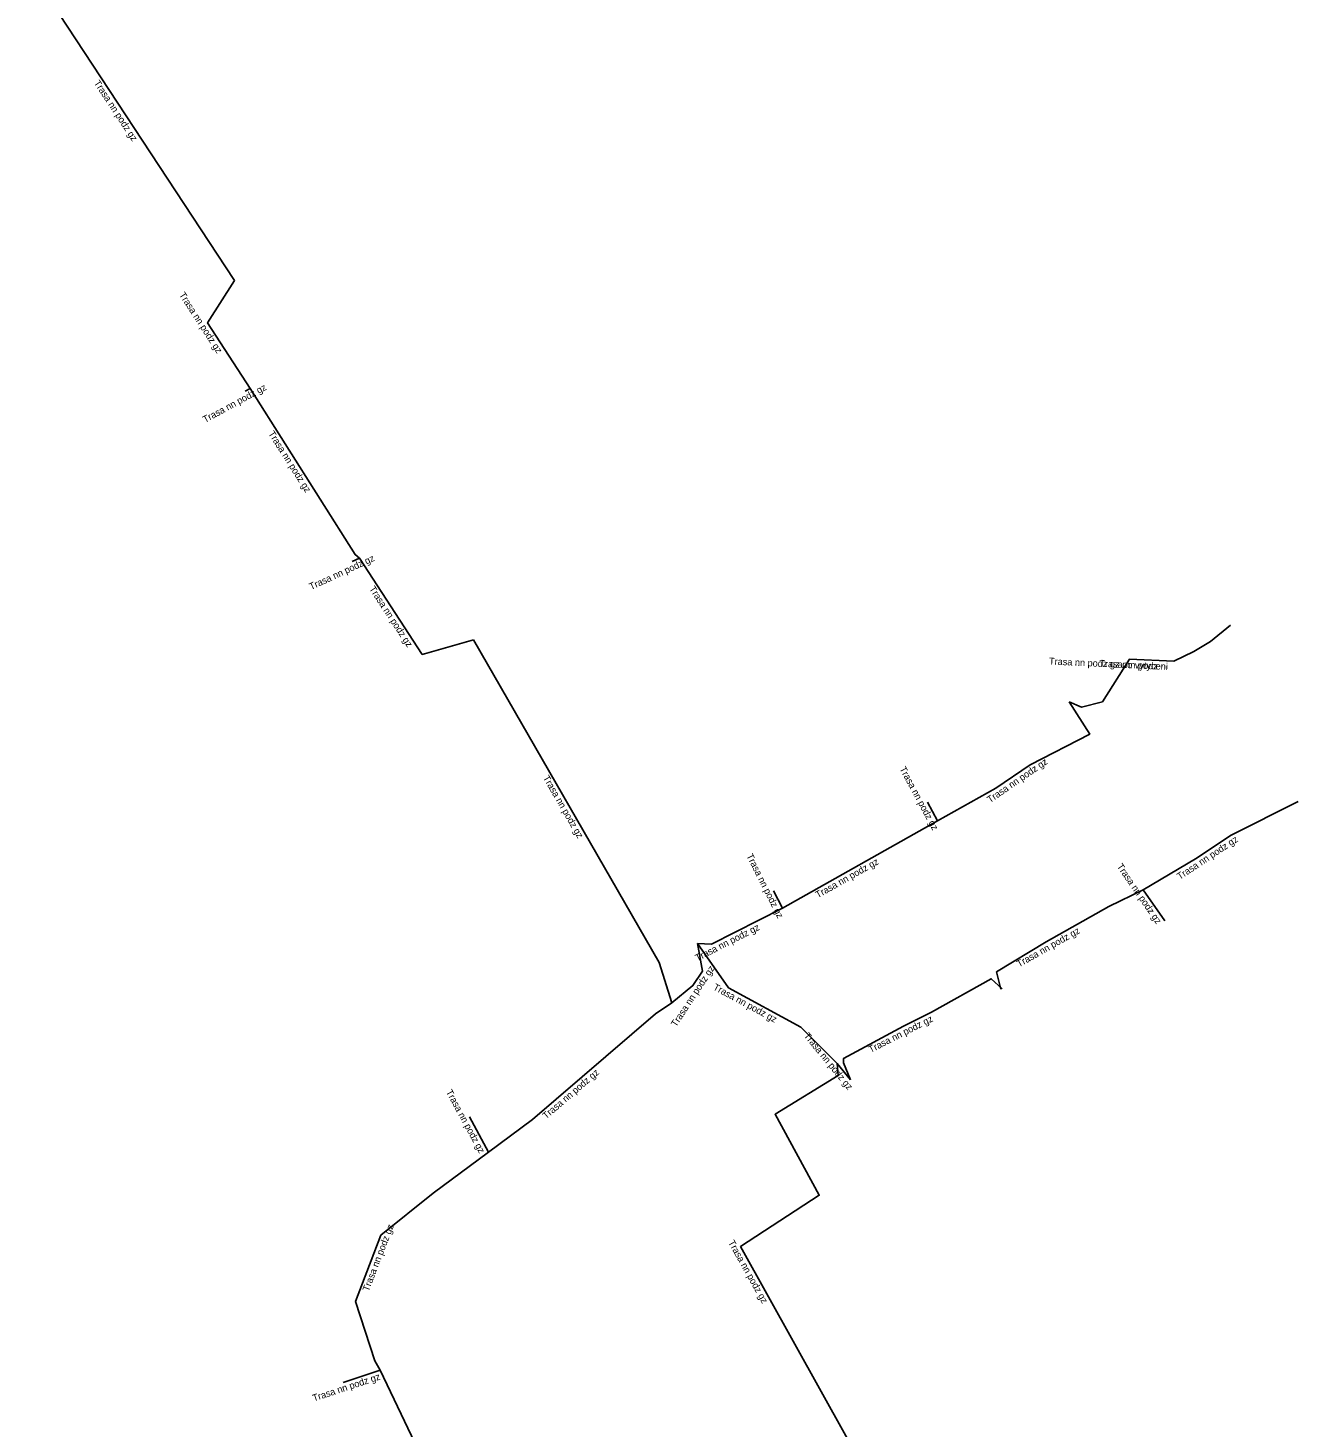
# Model space of a CAD drawing. Extents: x -467803 to -467116, y -1117596 to -1116713.
# Drawn here: x -467414.7 to -467321.9, y -1117056.5 to -1116954.2 of the extents above; entities that cross this region are included whole.
import ezdxf

# ---------------------------------------------------------------- set-up
doc = ezdxf.new("R2010")
doc.units = 0
for name, color, linetype in [('Popiskový text - Ostatní atributy Trasy', 7, 'Continuous'), ('Spojnice NN', 7, 'Continuous'), ('Spojnice VN', 7, 'Continuous')]:
    doc.layers.add(name, color=color, linetype=linetype)

msp = doc.modelspace()

# ---------------------------------------------------------------- linework, layer by layer
at = {"layer": 'Spojnice NN'}
for points in [[(-467399.6, -1116972.63), (-467413.05, -1116952.2), (-467414.68, -1116949.47)], [(-467398.45, -1116980.52), (-467401.56, -1116975.72), (-467399.6, -1116972.63)], [(-467398.45, -1116980.52), (-467398.8, -1116980.71)], [(-467390.46, -1116992.91), (-467390.77, -1116992.65), (-467398.45, -1116980.52)], [(-467390.46, -1116992.91), (-467390.98, -1116993.15)], [(-467382.11, -1116998.88), (-467385.86, -1116999.94), (-467390.46, -1116992.91)], [(-467338.58, -1117003.41), (-467337.68, -1117003.8), (-467336.15, -1117003.41), (-467334.17, -1117000.3), (-467330.93, -1117000.45), (-467329.47, -1116999.74), (-467328.25, -1116999), (-467326.79, -1116997.82)], [(-467338.58, -1117003.41), (-467337.68, -1117003.8), (-467336.15, -1117003.41), (-467334.17, -1117000.3), (-467330.93, -1117000.45), (-467329.47, -1116999.74), (-467328.25, -1116999), (-467326.79, -1116997.82)], [(-467367.61, -1117025.4), (-467368.54, -1117022.45), (-467382.11, -1116998.88)], [(-467338.58, -1117003.41), (-467337.07, -1117005.77), (-467341.44, -1117008.02), (-467343.93, -1117009.73), (-467348.21, -1117012.1)], [(-467348.21, -1117012.1), (-467348.94, -1117010.75)], [(-467333.16, -1117017.14), (-467329.34, -1117014.89), (-467326.73, -1117013.16), (-467321.85, -1117010.69)], [(-467348.21, -1117012.1), (-467359.54, -1117018.49)], [(-467359.54, -1117018.49), (-467360.18, -1117017.21)], [(-467343.57, -1117024.41), (-467343.9, -1117023.14), (-467340.26, -1117020.95), (-467335.69, -1117018.37), (-467333.16, -1117017.14)], [(-467333.16, -1117017.14), (-467331.59, -1117019.42)], [(-467359.54, -1117018.49), (-467364.72, -1117021.12), (-467365.74, -1117021.07)], [(-467365.74, -1117021.07), (-467365.39, -1117023.09), (-467366.08, -1117024.14), (-467367.61, -1117025.4)], [(-467365.74, -1117021.07), (-467363.48, -1117024.3), (-467358.19, -1117027.17), (-467355.53, -1117029.83)], [(-467354.55, -1117031.03), (-467355.07, -1117029.78), (-467355.07, -1117029.46), (-467350.69, -1117027.12), (-467348.65, -1117026.08), (-467344.27, -1117023.65), (-467343.48, -1117024.39)], [(-467367.61, -1117025.4), (-467368.81, -1117026.2), (-467377.81, -1117033.93), (-467381.02, -1117036.32)], [(-467355.53, -1117029.83), (-467355.46, -1117030.72), (-467360.07, -1117033.55), (-467356.85, -1117039.46), (-467362.6, -1117043.22), (-467354.77, -1117057.25), (-467353.07, -1117060.47), (-467350.03, -1117065.82), (-467350.26, -1117066.14)], [(-467355.53, -1117029.83), (-467354.55, -1117031.03)], [(-467381.02, -1117036.32), (-467382.42, -1117033.73)], [(-467381.02, -1117036.32), (-467385.06, -1117039.31), (-467388.9, -1117042.39), (-467390.74, -1117047.22), (-467389.33, -1117051.57), (-467388.95, -1117052.25)], [(-467388.95, -1117052.25), (-467391.64, -1117053.14)]]:
    msp.add_lwpolyline(points, dxfattribs=at)
at = {"layer": 'Spojnice VN'}
msp.add_lwpolyline([(-467365.34, -1117101.7), (-467388.95, -1117052.25)], dxfattribs=at)

# ---------------------------------------------------------------- texts
at = {"layer": 'Popiskový text - Ostatní atributy Trasy'}
for s, rotation, p in [('Trasa nn podz gz', 303.3738, (-467409.89, -1116958.19)), ('Trasa nn podz gz', 302.9119, (-467403.66, -1116973.67)), ('Trasa nn podz gz', 28.4731, (-467401.74, -1116983.04)), ('Trasa nn podz gz', 302.3645, (-467397.14, -1116983.81)), ('Trasa nn podz gz', 24.8013, (-467393.99, -1116995.25)), ('Trasa nn podz gz', 303.2115, (-467389.77, -1116995.15)), ('Trasa nn podz gz po vytyceni', 357.3493, (-467340.06, -1117000.68)), ('Trasa nn podz', 357.3493, (-467336.38, -1117000.85)), ('Trasa nn podz gz', 298.2408, (-467350.99, -1117008.3)), ('Trasa nn podz gz', 34.4792, (-467344.36, -1117010.82)), ('Trasa nn podz gz', 299.9423, (-467377.06, -1117008.96)), ('Trasa nn podz gz', 33.5378, (-467330.49, -1117016.43)), ('Trasa nn podz gz', 296.5651, (-467362.18, -1117014.66)), ('Trasa nn podz gz', 29.4225, (-467356.95, -1117017.77)), ('Trasa nn podz gz', 304.5512, (-467335.12, -1117015.44)), ('Trasa nn podz gz', 26.9277, (-467365.76, -1117022.38)), ('Trasa nn podz gz', 29.447, (-467342.24, -1117022.82)), ('Trasa nn podz gz', 56.6488, (-467367.31, -1117027.2)), ('Trasa nn podz gz', 331.5551, (-467364.65, -1117024.41)), ('Trasa nn podz gz', 26.9283, (-467353.09, -1117029.07)), ('Trasa nn podz gz', 309.4099, (-467358.01, -1117027.83)), ('Trasa nn podz gz', 40.6757, (-467376.81, -1117033.93)), ('Trasa nn podz gz', 298.4591, (-467384.15, -1117031.91)), ('Trasa nn podz gz', 69.0381, (-467389.78, -1117046.53)), ('Trasa nn podz gz', 299.1654, (-467363.52, -1117042.91)), ('Trasa nn podz gz', 18.3487, (-467393.79, -1117054.54))]:
    msp.add_text(s, height=0.5, rotation=rotation, dxfattribs=at).set_placement(p)

doc.saveas('drawing.dxf')
